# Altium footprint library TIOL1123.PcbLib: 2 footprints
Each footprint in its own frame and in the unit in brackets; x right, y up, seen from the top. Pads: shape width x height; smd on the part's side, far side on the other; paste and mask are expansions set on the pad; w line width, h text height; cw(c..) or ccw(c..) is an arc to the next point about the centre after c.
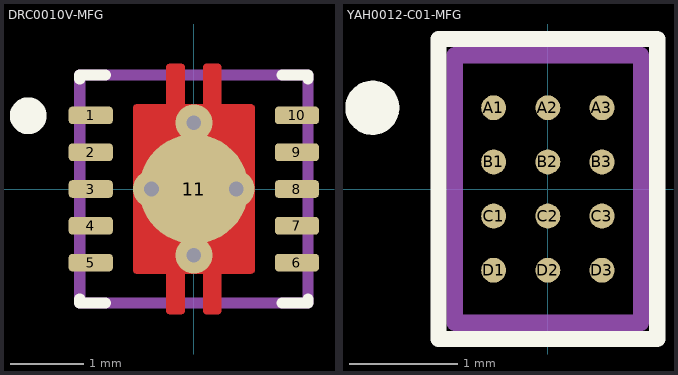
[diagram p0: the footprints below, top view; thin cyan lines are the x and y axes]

## DRC0010V-MFG [mm]
pads (11):
  rrect42% 0.6x0.24 smd paste+0 mask+0: 1(-1.4,1) 2(-1.4,0.5) 3(-1.4,0) 4(-1.4,-0.5) 5(-1.4,-1) 6(1.4,-1) 7(1.4,-0.5) 8(1.4,0) 9(1.4,0.5) 10(1.4,1)
  round 1.485 smd paste-1000 mask+0: 11(0,0)
via -0.575,0 diameter 0.5 hole 0.2
via 0.575,0 diameter 0.5 hole 0.2
via 0,0.9 diameter 0.5 hole 0.2
via 0,-0.9 diameter 0.5 hole 0.2
Top Layer:
  region: -0.825,1.1 -0.825,1.11 -0.817,1.128 -0.803,1.142 -0.785,1.15 -0.775,1.15 -0.375,1.15 -0.375,1.65 -0.375,1.66 -0.367,1.678 -0.353,1.692 -0.335,1.7 -0.325,1.7 -0.175,1.7 -0.165,1.7 -0.147,1.692 -0.133,1.678 -0.125,1.66 -0.125,1.65 -0.125,1.15 0.125,1.15 0.125,1.65 0.125,1.66 0.133,1.678 0.147,1.692 0.165,1.7 0.175,1.7 0.325,1.7 0.335,1.7 0.353,1.692 0.367,1.678 0.375,1.66 0.375,1.65 0.375,1.15 0.775,1.15 0.785,1.15 0.803,1.142 0.817,1.128 0.825,1.11 0.825,1.1 0.825,-1.1 0.825,-1.11 0.817,-1.128 0.803,-1.142 0.785,-1.15 0.775,-1.15 0.375,-1.15 0.375,-1.65 0.375,-1.66 0.367,-1.678 0.353,-1.692 0.335,-1.7 0.325,-1.7 0.175,-1.7 0.165,-1.7 0.147,-1.692 0.133,-1.678 0.125,-1.66 0.125,-1.65 0.125,-1.15 -0.125,-1.15 -0.125,-1.65 -0.125,-1.66 -0.133,-1.678 -0.147,-1.692 -0.165,-1.7 -0.175,-1.7 -0.325,-1.7 -0.335,-1.7 -0.353,-1.692 -0.367,-1.678 -0.375,-1.66 -0.375,-1.65 -0.375,-1.15 -0.775,-1.15 -0.785,-1.15 -0.803,-1.142 -0.817,-1.128 -0.825,-1.11 -0.825,-1.1
Top Overlay:
  circle w0.25: c-2.25,0.995 r0.125
  lines w0.15: -1.55,-1.495 -1.55,-1.55 -1.2,-1.55 ; -1.55,1.495 -1.55,1.55 -1.2,1.55 ; 1.2,-1.55 1.55,-1.55 1.55,-1.495 ; 1.2,1.55 1.55,1.55 1.55,1.495
Top Paste:
  drawing of 6 lines, arcs and shapes, not listed
Mechanical 5:
  lines w0.15: -1.55,-1.55 1.55,-1.55 1.55,1.55 -1.55,1.55 -1.55,-1.55
  text ".Designator" at 0,0 h0.5
3D body "IC_TIOS1025DRCR_VSON10.STEP": height 0.25, standoff 0, extent -1.8,-1.8 1.8,1.8

## YAH0012-C01-MFG [mm]
pads (12):
  round 0.23 smd paste-1000 mask+0.05: A1(-0.5,0.75) A2(0,0.75) A3(0.5,0.75) B1(-0.5,0.25) B2(0,0.25) B3(0.5,0.25) C1(-0.5,-0.25) C2(0,-0.25) C3(0.5,-0.25) D1(-0.5,-0.75) D2(0,-0.75) D3(0.5,-0.75)
Top Overlay:
  circle w0.25: c-1.62,0.75 r0.125
  lines w0.15: -1.01,-1.385 1.01,-1.385 1.01,1.385 -1.01,1.385 -1.01,-1.385
Top Paste:
  drawing of 12 lines, arcs and shapes, not listed
Mechanical 5:
  lines w0.15: -0.86,-1.235 0.86,-1.235 0.86,1.235 -0.86,1.235 -0.86,-1.235
  text ".Designator" at 0,0 h0.5
3D body "IC_TIOS1023LYAHR_DSBGA12.STEP": height 0.25, standoff 0, extent -1.36,-1.735 1.36,1.735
